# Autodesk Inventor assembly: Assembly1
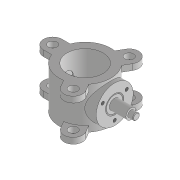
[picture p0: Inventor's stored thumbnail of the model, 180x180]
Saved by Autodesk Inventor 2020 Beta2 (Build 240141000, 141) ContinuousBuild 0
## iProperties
Created: 2019-03
Part Number: Assembly1
Document SubType Name: Assembly
Designer: LENOVO-CADCIM
Author: LENOVO-CADCIM
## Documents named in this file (3)
- D:\Autodesk Inventor_2020\c09\Butterfly Valve\Assembly1.iam
- D:\Autodesk Inventor_2020\c09\Butterfly Valve\Body.ipt
- D:\Autodesk Inventor_2020\c09\Butterfly Valve\Shaft.ipt
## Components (2 placed, 2 different names)
1. Body:1 — Insert:1
2. Shaft:1 — Insert:1
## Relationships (1: Insert 1)
- Insert:1: Body:1 ↔ Shaft:1
